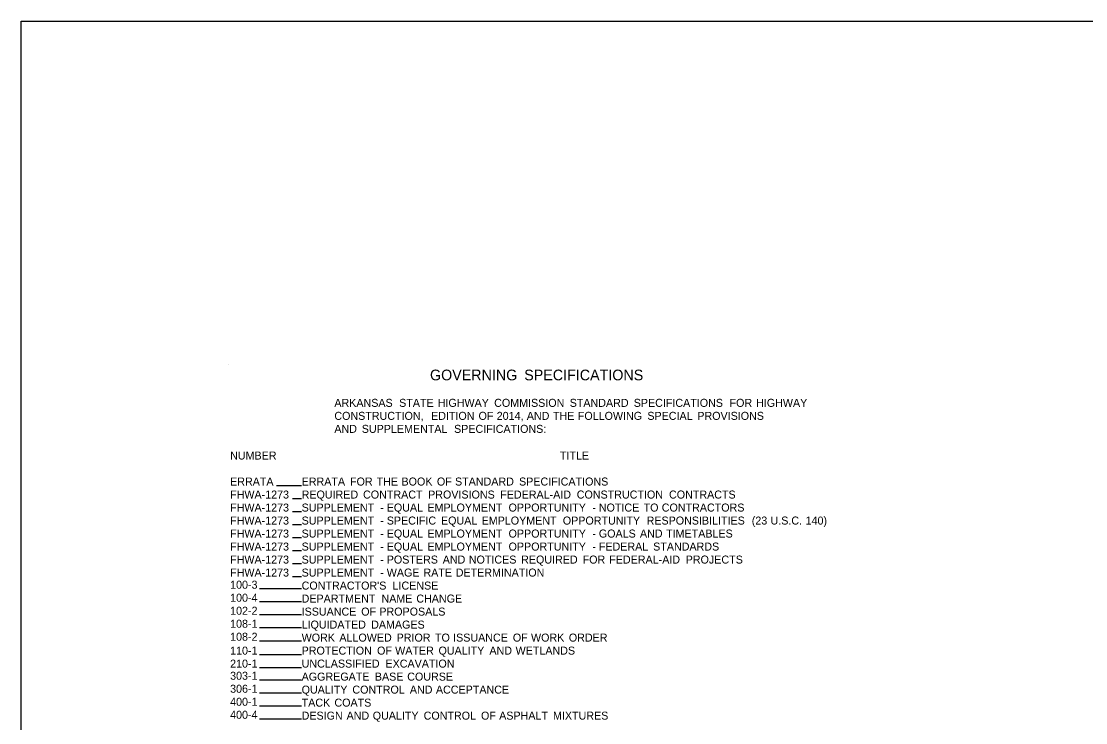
# Model space of a CAD drawing. Extents: x 1955683 to 1956002, y 566394 to 566602.
# Drawn here: x 1955683.4 to 1955842.9, y 566496.8 to 566602 of the extents above; entities that cross this region are included whole.
import ezdxf

# ---------------------------------------------------------------- set-up
doc = ezdxf.new("R2010")
doc.units = 0
doc.layers.add('Default', color=7, linetype='Continuous')
doc.layers.add('R_Border Prem', color=7, linetype='Continuous')

msp = doc.modelspace()

# ---------------------------------------------------------------- linework, layer by layer
at = {"layer": 'Default'}
for p, q in [((1955714.48, 566550.45), (1955714.48, 566550.45)), ((1955721.61, 566532.36), (1955725.4, 566532.36)), ((1955724.02, 566530.41), (1955725.4, 566530.41)), ((1955724.02, 566528.46), (1955725.4, 566528.46)), ((1955724.02, 566526.51), (1955725.4, 566526.51)), ((1955724.02, 566524.56), (1955725.4, 566524.56)), ((1955724.02, 566522.61), (1955725.4, 566522.61)), ((1955724.02, 566520.66), (1955725.4, 566520.66)), ((1955724.02, 566518.71), (1955725.4, 566518.71)), ((1955719.09, 566516.9), (1955725.4, 566516.9)), ((1955719.09, 566514.95), (1955725.4, 566514.95)), ((1955719.09, 566513), (1955725.4, 566513)), ((1955719.09, 566511.05), (1955725.4, 566511.05)), ((1955719.09, 566509.1), (1955725.4, 566509.1)), ((1955719.09, 566507.01), (1955725.4, 566507.01)), ((1955719.09, 566505.06), (1955725.4, 566505.06)), ((1955719.09, 566503.25), (1955725.4, 566503.25)), ((1955719.09, 566501.3), (1955725.4, 566501.3)), ((1955719.09, 566499.35), (1955725.4, 566499.35)), ((1955719.09, 566497.4), (1955725.4, 566497.4))]:
    msp.add_line(p, q, dxfattribs=at)
at = {"layer": 'R_Border Prem'}
msp.add_lwpolyline([(1956002.45, 566561.79), (1956002.45, 566393.51), (1955683.38, 566393.51), (1955683.38, 566601.97), (1955920.19, 566601.97), (1955920.19, 566592.09), (1955955.71, 566592.09), (1955955.71, 566588.52), (1955959.35, 566588.52), (1955959.35, 566589.17), (1955974.89, 566589.17)], dxfattribs=at)

# ---------------------------------------------------------------- texts
at = {"layer": 'Default'}
for s, height, p in [('GOVERNING', 1.6, (1955744.64, 566548.14)), (' SPECIFICATIONS', 1.6, (1955758.17, 566548.14)), ('           ARKANSAS', 1.2, (1955725.4, 566544.16)), (' STATE', 1.2, (1955739.57, 566544.16)), (' HIGHWAY', 1.2, (1955745.35, 566544.16)), (' COMMISSION', 1.2, (1955753.81, 566544.16)), (' STANDARD', 1.2, (1955765.13, 566544.16)), (' SPECIFICATIONS', 1.2, (1955774.73, 566544.16)), (' FOR', 1.2, (1955789.09, 566544.16)), (' HIGHWAY', 1.2, (1955793.07, 566544.16)), ('           CONSTRUCTION,', 1.2, (1955725.4, 566542.21)), (' EDITION', 1.2, (1955744.35, 566542.21)), (' OF', 1.2, (1955751.47, 566542.21)), (' 2014,', 1.2, (1955754.19, 566542.21)), (' AND', 1.2, (1955758.7, 566542.21)), (' THE', 1.2, (1955762.62, 566542.21)), (' FOLLOWING', 1.2, (1955766.35, 566542.21)), (' SPECIAL', 1.2, (1955776.77, 566542.21)), (' PROVISIONS', 1.2, (1955784.26, 566542.21)), ('           AND', 1.2, (1955725.4, 566540.26)), (' SUPPLEMENTAL', 1.2, (1955733.97, 566540.26)), (' SPECIFICATIONS:', 1.2, (1955747.8, 566540.26)), ('NUMBER', 1.2, (1955714.68, 566536.26)), ('TITLE', 1.2, (1955764.11, 566536.26)), ('ERRATA', 1.2, (1955714.68, 566532.36)), ('ERRATA', 1.2, (1955725.4, 566532.36)), (' FOR', 1.2, (1955732.21, 566532.36)), (' THE', 1.2, (1955736.19, 566532.36)), (' BOOK', 1.2, (1955739.92, 566532.36)), (' OF', 1.2, (1955745.23, 566532.36)), (' STANDARD', 1.2, (1955747.94, 566532.36)), (' SPECIFICATIONS', 1.2, (1955757.54, 566532.36)), ('FHWA-1273', 1.2, (1955714.68, 566530.41)), ('REQUIRED', 1.2, (1955725.4, 566530.41)), (' CONTRACT', 1.2, (1955734.16, 566530.41)), (' PROVISIONS', 1.2, (1955743.91, 566530.41)), (' FEDERAL-AID', 1.2, (1955754.72, 566530.41)), (' CONSTRUCTION', 1.2, (1955766.19, 566530.41)), (' CONTRACTS', 1.2, (1955780.02, 566530.41)), ('FHWA-1273', 1.2, (1955714.68, 566528.46)), ('SUPPLEMENT', 1.2, (1955725.4, 566528.46)), (' -', 1.2, (1955736.74, 566528.46)), (' EQUAL', 1.2, (1955737.71, 566528.46)), (' EMPLOYMENT', 1.2, (1955743.8, 566528.46)), (' OPPORTUNITY', 1.2, (1955755.97, 566528.46)), (' -', 1.2, (1955768.53, 566528.46)), (' NOTICE', 1.2, (1955769.5, 566528.46)), (' TO', 1.2, (1955776.21, 566528.46)), (' CONTRACTORS', 1.2, (1955778.93, 566528.46)), ('FHWA-1273', 1.2, (1955714.68, 566526.51)), ('SUPPLEMENT', 1.2, (1955725.4, 566526.51)), (' SPECIFIC', 1.2, (1955737.71, 566526.51)), (' EQUAL', 1.2, (1955745.84, 566526.51)), (' EMPLOYMENT', 1.2, (1955751.93, 566526.51)), (' OPPORTUNITY', 1.2, (1955764.1, 566526.51)), (' RESPONSIBILITIES', 1.2, (1955776.66, 566526.51)), (' (23', 1.2, (1955792.42, 566526.51)), (' U.S.C.', 1.2, (1955795.23, 566526.51)), (' 140)', 1.2, (1955800.49, 566526.51)), ('FHWA-1273', 1.2, (1955714.68, 566524.56)), ('SUPPLEMENT', 1.2, (1955725.4, 566524.56)), (' -', 1.2, (1955736.74, 566526.51)), (' EQUAL', 1.2, (1955737.71, 566524.56)), (' EMPLOYMENT', 1.2, (1955743.8, 566524.56)), (' OPPORTUNITY', 1.2, (1955755.97, 566524.56)), (' GOALS', 1.2, (1955769.5, 566524.56)), (' AND', 1.2, (1955775.66, 566524.56)), (' TIMETABLES', 1.2, (1955779.58, 566524.56)), (' -', 1.2, (1955736.74, 566524.56)), (' -', 1.2, (1955768.53, 566524.56)), ('FHWA-1273', 1.2, (1955714.68, 566522.61)), ('SUPPLEMENT', 1.2, (1955725.4, 566522.61)), (' -', 1.2, (1955736.74, 566522.61)), (' EQUAL', 1.2, (1955737.71, 566522.61)), (' EMPLOYMENT', 1.2, (1955743.8, 566522.61)), (' OPPORTUNITY', 1.2, (1955755.97, 566522.61)), (' -', 1.2, (1955768.53, 566522.61)), (' FEDERAL', 1.2, (1955769.5, 566522.61)), (' STANDARDS', 1.2, (1955777.64, 566522.61)), ('FHWA-1273', 1.2, (1955714.68, 566520.66)), ('SUPPLEMENT', 1.2, (1955725.4, 566520.66)), (' -', 1.2, (1955736.74, 566520.66)), (' POSTERS', 1.2, (1955737.71, 566520.66)), (' AND', 1.2, (1955746.1, 566520.66)), (' NOTICES', 1.2, (1955750.01, 566520.66)), (' REQUIRED', 1.2, (1955757.85, 566520.66)), (' FOR', 1.2, (1955767.07, 566520.66)), (' FEDERAL-AID', 1.2, (1955771.06, 566520.66)), (' PROJECTS', 1.2, (1955782.52, 566520.66)), ('FHWA-1273', 1.2, (1955714.68, 566518.71)), ('SUPPLEMENT', 1.2, (1955725.4, 566518.71)), (' -', 1.2, (1955736.74, 566518.71)), (' WAGE', 1.2, (1955737.71, 566518.71)), (' RATE', 1.2, (1955743.21, 566518.71)), (' DETERMINATION', 1.2, (1955748.05, 566518.71)), ('100-3', 1.2, (1955714.68, 566516.89)), ("CONTRACTOR'S", 1.2, (1955725.4, 566516.76)), (' LICENSE', 1.2, (1955738.58, 566516.76)), ('100-4', 1.2, (1955714.68, 566514.94)), ('DEPARTMENT', 1.2, (1955725.4, 566514.81)), (' NAME', 1.2, (1955736.92, 566514.81)), (' CHANGE', 1.2, (1955742.14, 566514.81)), ('102-2', 1.2, (1955714.68, 566512.99)), ('ISSUANCE', 1.2, (1955725.4, 566512.86)), (' OF', 1.2, (1955733.88, 566512.86)), (' PROPOSALS', 1.2, (1955736.6, 566512.86)), ('108-1', 1.2, (1955714.68, 566511.04)), ('LIQUIDATED', 1.2, (1955725.4, 566510.91)), (' DAMAGES', 1.2, (1955735.37, 566510.91)), ('108-2', 1.2, (1955714.68, 566509.09)), ('WORK', 1.2, (1955725.4, 566508.96)), (' ALLOWED', 1.2, (1955730.61, 566508.96)), (' PRIOR', 1.2, (1955739.19, 566508.96)), (' TO', 1.2, (1955744.94, 566508.96)), (' ISSUANCE', 1.2, (1955747.66, 566508.96)), (' OF', 1.2, (1955756.61, 566508.96)), (' WORK', 1.2, (1955759.33, 566508.96)), (' ORDER', 1.2, (1955765, 566508.96)), ('110-1', 1.2, (1955714.68, 566507.01)), ('PROTECTION', 1.2, (1955725.4, 566507.01)), (' OF', 1.2, (1955736.26, 566507.01)), (' WATER', 1.2, (1955738.97, 566507.01)), (' QUALITY', 1.2, (1955745.47, 566507.01)), (' AND', 1.2, (1955753.1, 566507.01)), (' WETLANDS', 1.2, (1955757.02, 566507.01)), ('210-1', 1.2, (1955714.68, 566505.06)), ('UNCLASSIFIED', 1.2, (1955725.4, 566505.06)), (' EXCAVATION', 1.2, (1955737.52, 566505.06)), ('303-1', 1.2, (1955714.68, 566503.24)), ('AGGREGATE', 1.2, (1955725.4, 566503.11)), (' BASE', 1.2, (1955735.93, 566503.11)), (' COURSE', 1.2, (1955740.78, 566503.11)), ('306-1', 1.2, (1955714.68, 566501.29)), ('QUALITY', 1.2, (1955725.4, 566501.16)), (' CONTROL', 1.2, (1955732.56, 566501.16)), (' AND', 1.2, (1955741.17, 566501.16)), (' ACCEPTANCE', 1.2, (1955745.08, 566501.16)), ('400-1', 1.2, (1955714.68, 566499.34)), ('TACK', 1.2, (1955725.4, 566499.21)), (' COATS', 1.2, (1955729.87, 566499.21)), ('400-4', 1.2, (1955714.68, 566497.39)), ('DESIGN', 1.2, (1955725.4, 566497.26)), (' AND', 1.2, (1955731.69, 566497.26)), (' QUALITY', 1.2, (1955735.61, 566497.26)), (' CONTROL', 1.2, (1955743.24, 566497.26)), (' OF', 1.2, (1955751.84, 566497.26)), (' ASPHALT', 1.2, (1955754.56, 566497.26)), (' MIXTURES', 1.2, (1955762.63, 566497.26))]:
    msp.add_text(s, height=height, dxfattribs=at).set_placement(p)

doc.saveas('drawing.dxf')
